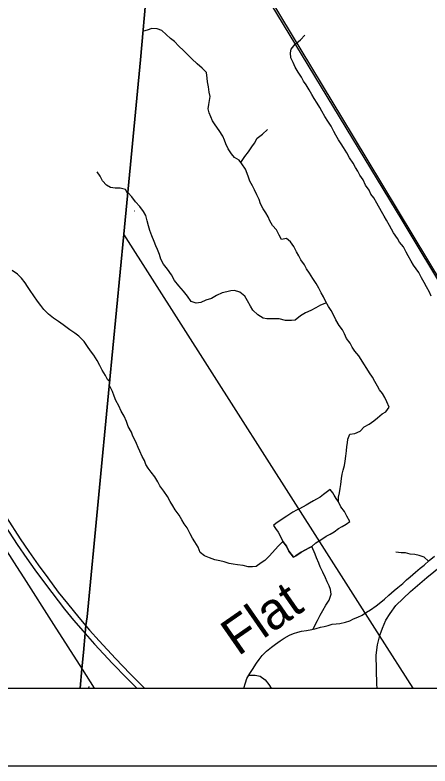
# Model space of a CAD drawing. Extents: x 0 to 34, y 0 to 22.
# Drawn here: x 2.622 to 3.154, y 14 to 14.963 of the extents above; entities that cross this region are included whole.
import ezdxf

# ---------------------------------------------------------------- set-up
doc = ezdxf.new("R2010")
doc.units = 0
for name, color, linetype in [('GM_X_Corporation', 7, 'Continuous'), ('GM_X_Minor_Lake', 7, 'Continuous'), ('GM_X_Minor_River', 7, 'Continuous'), ('GM_X_Minor_River_Text', 7, 'Continuous'), ('GM_X_Rail_Line', 7, 'Continuous'), ('GM_X_State_Route', 7, 'Continuous'), ('GM_X_US_Route', 7, 'Continuous'), ('SH_Data', 7, 'Continuous')]:
    doc.layers.add(name, color=color, linetype=linetype)

msp = doc.modelspace()

# ---------------------------------------------------------------- linework, layer by layer
at = {"layer": 'GM_X_Corporation'}
for points in [[(2.1, 20.9), (2.1, 14.1), (2.70517, 14.1), (2.70761, 14.12453), (2.70949, 14.14572), (2.71149, 14.17029), (2.71244, 14.18008), (2.71408, 14.19146), (2.74262, 14.48729), (2.76121, 14.68204), (2.78252, 14.90567), (2.79096, 14.99744), (2.84444, 15.57923), (2.89388, 16.10066)], [(2.89388, 16.10066), (2.84444, 15.57923), (2.79096, 14.99744), (2.78252, 14.90567), (2.76121, 14.68204), (2.74262, 14.48729), (2.71408, 14.19146), (2.71244, 14.18008), (2.71149, 14.17029), (2.70949, 14.14572), (2.70761, 14.12453), (2.70517, 14.1), (8.9, 14.1)]]:
    msp.add_lwpolyline(points, dxfattribs=at)
for points in [[(2.1, 15.03648), (2.1, 14.1), (2.70517, 14.1), (2.70761, 14.12453), (2.70949, 14.14572), (2.71149, 14.17029), (2.71244, 14.18008), (2.71408, 14.19146), (2.74262, 14.48729), (2.76121, 14.68204), (2.78252, 14.90567), (2.79096, 14.99744), (2.14799, 15.03391), (2.14359, 15.03416), (2.13937, 15.03437), (2.12058, 15.03531), (2.12001, 15.03535)], [(2.70517, 14.1), (3.13256, 14.1), (3.08947, 14.16754), (2.76121, 14.68204), (2.74262, 14.48729), (2.71408, 14.19146), (2.71244, 14.18008), (2.71149, 14.17029), (2.70949, 14.14572), (2.70761, 14.12453)]]:
    msp.add_lwpolyline(points, close=True, dxfattribs=at)
at = {"layer": 'GM_X_Minor_Lake'}
for points in [[(3.0367, 14.33863), (3.0337, 14.34301), (3.03126, 14.34738), (3.02938, 14.35023), (3.02599, 14.35442), (3.01762, 14.34802), (3.01305, 14.34482), (3.00868, 14.34238), (3.0045, 14.33994), (2.99956, 14.33712), (2.99519, 14.33468), (2.98682, 14.3298), (2.98283, 14.32811), (2.97827, 14.32548), (2.97542, 14.32398), (2.97048, 14.32059), (2.96572, 14.31759), (2.96135, 14.31439), (2.95659, 14.31138), (2.95317, 14.30855), (2.95599, 14.30456), (2.95937, 14.29999), (2.96181, 14.29505), (2.96537, 14.28783)], [(3.00234, 14.2816), (3.00761, 14.2861), (3.01408, 14.29005), (3.02092, 14.29494), (3.02586, 14.29737), (3.031, 14.30019), (3.03651, 14.30452), (3.04146, 14.30715), (3.04659, 14.31034), (3.05109, 14.3136), (3.04759, 14.32038), (3.04422, 14.32647), (3.03989, 14.33255), (3.0367, 14.33863)], [(2.96537, 14.28783), (2.96988, 14.28175), (2.97288, 14.27548), (2.97913, 14.26766), (2.98194, 14.26955), (2.9886, 14.27407), (2.9943, 14.27726), (2.99905, 14.2797), (3.00234, 14.2816)]]:
    msp.add_lwpolyline(points, dxfattribs=at)
at = {"layer": 'GM_X_Minor_River'}
msp.add_line((2.71629, 14.1), (2.71669, 14.10206), dxfattribs=at)
for points in [[(2.88823, 14.80795), (2.88353, 14.81498), (2.87827, 14.82241), (2.87526, 14.82735), (2.87282, 14.83267), (2.87095, 14.83761), (2.86947, 14.84273), (2.87025, 14.84842), (2.87123, 14.85353), (2.87201, 14.85865), (2.87071, 14.86434), (2.86999, 14.87098), (2.86851, 14.87743), (2.86834, 14.88236), (2.86724, 14.88938), (2.86178, 14.89491), (2.85536, 14.90044), (2.84858, 14.90692), (2.84235, 14.91283), (2.83764, 14.91778), (2.8318, 14.92312), (2.82614, 14.92903), (2.82124, 14.93322), (2.81558, 14.93837), (2.80992, 14.94314), (2.80406, 14.94563), (2.79743, 14.94585), (2.79135, 14.94361), (2.78633, 14.94233)], [(3.15563, 14.6026), (3.15358, 14.60773), (3.14964, 14.61476), (3.14644, 14.6199), (3.14307, 14.62617), (3.13969, 14.63282), (3.13612, 14.63758), (3.13311, 14.64252), (3.12973, 14.64747), (3.12616, 14.65431), (3.12354, 14.65907), (3.11997, 14.66572), (3.11508, 14.672), (3.11226, 14.67675), (3.10737, 14.68379), (3.10475, 14.68854), (3.10193, 14.6933), (3.09818, 14.69995), (3.09517, 14.70509), (3.09179, 14.71117), (3.08579, 14.72181), (3.08184, 14.72866), (3.07827, 14.73361), (3.07583, 14.73836), (3.07151, 14.74501), (3.06813, 14.75167), (3.064, 14.75775), (3.06156, 14.7627), (3.05855, 14.76764), (3.05536, 14.77296), (3.05066, 14.78019), (3.04728, 14.78647), (3.04296, 14.79312), (3.03995, 14.79788), (3.03657, 14.8032), (3.03338, 14.8091), (3.03075, 14.81385), (3.02738, 14.8205), (3.02286, 14.82697), (3.01929, 14.83287), (3.01535, 14.83971), (3.01272, 14.84465), (3.00953, 14.84998), (3.00558, 14.85607), (3.00239, 14.8612), (2.99901, 14.86709), (2.99525, 14.87356), (2.99187, 14.87851), (2.98905, 14.88364), (2.98491, 14.88973), (2.98116, 14.89638), (2.97835, 14.90246), (2.97572, 14.90835), (2.975, 14.91461), (2.97616, 14.91954), (2.98131, 14.92577), (2.98797, 14.93142), (2.99349, 14.93746)], [(2.91137, 14.77415), (2.91633, 14.78164), (2.9211, 14.78787), (2.92568, 14.79411), (2.92873, 14.79902), (2.93256, 14.80526), (2.9394, 14.81015), (2.94569, 14.81637)], [(3.00234, 14.2816), (3.00761, 14.2861), (3.01408, 14.29005), (3.02092, 14.29494), (3.02586, 14.29737), (3.031, 14.30019), (3.03651, 14.30452), (3.04146, 14.30715), (3.04659, 14.31034), (3.05109, 14.3136), (3.04759, 14.32038), (3.04422, 14.32647), (3.03989, 14.33255), (3.0367, 14.33863), (3.03674, 14.34489), (3.03791, 14.35038), (3.0387, 14.35606), (3.03967, 14.36117), (3.04047, 14.36856), (3.04145, 14.37443), (3.04262, 14.37954), (3.04435, 14.38522), (3.04533, 14.39109), (3.04594, 14.39734), (3.04711, 14.40434), (3.04752, 14.40965), (3.04831, 14.41457), (3.04871, 14.41931), (3.0514, 14.42555), (3.05746, 14.42628), (3.06449, 14.42927), (3.06964, 14.43493), (3.07591, 14.4385), (3.082, 14.44264), (3.08675, 14.4464), (3.09285, 14.45187), (3.0976, 14.45412), (3.10161, 14.46016), (3.09881, 14.46719), (3.09618, 14.4727), (3.09318, 14.47783), (3.08923, 14.48259), (3.08679, 14.48734), (3.08341, 14.49305), (3.08022, 14.49875), (3.07665, 14.50426), (3.07308, 14.50997), (3.06933, 14.51567), (3.06594, 14.52119), (3.06294, 14.52594), (3.05767, 14.53203), (3.05428, 14.53698), (3.05166, 14.54211), (3.04677, 14.5482), (3.04434, 14.55428), (3.0419, 14.55922), (3.03757, 14.56512), (3.03344, 14.57215), (3.02988, 14.57937), (3.02725, 14.58412), (3.02368, 14.58945), (3.02012, 14.5961), (3.01731, 14.60161), (3.0143, 14.60675), (3.01131, 14.61302), (3.00792, 14.61872), (3.00379, 14.62519), (2.99928, 14.63203), (2.99571, 14.63755), (2.9929, 14.64268), (2.98838, 14.64934), (2.98576, 14.65428), (2.98275, 14.65923), (2.97919, 14.66626), (2.97524, 14.67234), (2.96977, 14.67654), (2.96351, 14.67506), (2.96051, 14.68076), (2.95713, 14.6876), (2.95205, 14.69312), (2.94848, 14.69921), (2.94661, 14.70434), (2.94361, 14.70947), (2.94004, 14.7146), (2.93647, 14.72107), (2.93498, 14.72638), (2.93179, 14.73266), (2.92899, 14.73893), (2.92655, 14.74406), (2.92298, 14.75014), (2.92111, 14.75508), (2.91962, 14.76001), (2.91738, 14.76552), (2.91287, 14.77218), (2.9091, 14.77713), (2.90306, 14.78057), (2.89948, 14.78533), (2.89534, 14.79142), (2.89235, 14.79807), (2.89048, 14.80282), (2.88823, 14.80795)], [(2.76658, 14.73378), (2.7635, 14.73923), (2.75669, 14.74124), (2.75004, 14.74096), (2.74416, 14.742), (2.73907, 14.74474), (2.73384, 14.75051), (2.73089, 14.75644), (2.72718, 14.76219)], [(3.02131, 14.59389), (3.01365, 14.59121), (3.00776, 14.58764), (3.00111, 14.58426), (2.99446, 14.58126), (2.988, 14.5775), (2.98114, 14.57185), (2.97622, 14.5715), (2.96864, 14.57154), (2.9605, 14.57367), (2.95538, 14.5735), (2.95008, 14.57334), (2.94477, 14.57337), (2.93985, 14.57434), (2.93305, 14.57855), (2.92683, 14.58483), (2.92364, 14.58959), (2.92008, 14.59662), (2.91651, 14.60251), (2.91009, 14.60766), (2.90328, 14.60978), (2.89855, 14.60962), (2.89342, 14.60832), (2.88735, 14.60683), (2.88013, 14.60327), (2.87367, 14.5997), (2.86665, 14.59727), (2.86019, 14.59446), (2.85412, 14.59373), (2.84769, 14.59585), (2.84318, 14.60251), (2.83791, 14.60898), (2.83188, 14.61603), (2.82623, 14.6225), (2.82248, 14.62991), (2.81741, 14.63733), (2.81233, 14.6438), (2.80876, 14.65007), (2.8069, 14.65596), (2.80428, 14.66223), (2.80222, 14.66735), (2.80017, 14.67286), (2.79736, 14.68008), (2.79456, 14.68673), (2.79288, 14.6928), (2.7914, 14.69906), (2.78954, 14.70609), (2.78673, 14.71103), (2.78184, 14.71769), (2.77637, 14.72378), (2.77167, 14.72987), (2.76672, 14.73526)], [(2.77474, 14.71205), (2.77487, 14.71191)], [(2.74358, 14.4927), (2.74017, 14.49577), (2.73797, 14.50073), (2.73371, 14.50782), (2.73056, 14.51356), (2.72724, 14.51988), (2.72279, 14.52678), (2.7185, 14.53234), (2.7146, 14.5381), (2.71033, 14.54443), (2.7034, 14.55117), (2.69833, 14.55505), (2.69194, 14.55951), (2.68329, 14.56572), (2.67766, 14.57017), (2.67107, 14.57426), (2.6645, 14.57948), (2.6587, 14.58545), (2.65498, 14.59044), (2.65051, 14.59621), (2.64567, 14.60311), (2.64103, 14.61002), (2.63787, 14.61481), (2.63472, 14.61979), (2.62987, 14.62575), (2.62482, 14.63076), (2.61786, 14.63561)], [(3.00434, 14.17562), (3.00665, 14.18111), (3.0099, 14.18678), (3.01316, 14.1934), (3.0166, 14.19925), (3.02043, 14.20606), (3.02482, 14.21286), (3.02733, 14.22023), (3.0266, 14.2263), (3.02455, 14.23105), (3.0223, 14.23618), (3.02006, 14.2415), (3.0165, 14.24872), (3.01331, 14.25537), (3.01163, 14.26011), (3.00864, 14.26695), (3.00677, 14.2717), (3.00234, 14.2816), (2.99905, 14.2797), (2.9943, 14.27726), (2.9886, 14.27407), (2.98194, 14.26955), (2.97913, 14.26766), (2.97288, 14.27548), (2.96988, 14.28175), (2.96537, 14.28783), (2.95908, 14.2818), (2.94802, 14.26935), (2.94212, 14.26351), (2.93736, 14.26069), (2.93108, 14.25598), (2.92634, 14.25544), (2.92085, 14.25547), (2.91423, 14.25721), (2.90722, 14.25819), (2.90135, 14.25898), (2.89624, 14.25976), (2.88981, 14.26169), (2.88451, 14.26304), (2.87808, 14.26459), (2.87127, 14.26709), (2.86465, 14.26959), (2.85918, 14.27379), (2.85657, 14.28062), (2.85244, 14.28747), (2.84943, 14.29222), (2.84643, 14.29754), (2.84249, 14.30533), (2.83854, 14.31047), (2.83573, 14.31579), (2.83217, 14.32187), (2.82728, 14.32834), (2.82408, 14.33347), (2.82071, 14.33937), (2.81752, 14.34583), (2.81282, 14.35248), (2.80736, 14.35915), (2.80474, 14.36446), (2.80099, 14.37093), (2.79628, 14.37702), (2.79233, 14.38196), (2.78933, 14.38672), (2.78765, 14.39184), (2.78502, 14.39697), (2.78165, 14.40362), (2.77978, 14.40837), (2.77754, 14.4135), (2.77548, 14.41825), (2.77285, 14.42319), (2.77098, 14.42794), (2.76686, 14.43554), (2.76462, 14.44199), (2.76162, 14.44864), (2.75787, 14.45492), (2.75468, 14.46176), (2.75093, 14.46879), (2.74869, 14.47448), (2.74683, 14.48018), (2.74364, 14.48645), (2.74307, 14.48742)], [(2.91532, 14.1), (2.91736, 14.10672), (2.91891, 14.11201), (2.92292, 14.11863), (2.92655, 14.12392), (2.93134, 14.13185), (2.93496, 14.13676), (2.93878, 14.14186), (2.94412, 14.14713), (2.95078, 14.15241), (2.95573, 14.15617), (2.96181, 14.16069), (2.96695, 14.16388), (2.97379, 14.16783), (2.97892, 14.16989), (2.98442, 14.17175), (2.98936, 14.17286), (2.99561, 14.17397), (3.00263, 14.17526), (3.00794, 14.17637), (3.01345, 14.17786), (3.01838, 14.17897), (3.0235, 14.18027), (3.02844, 14.18176), (3.03356, 14.18211), (3.03849, 14.18284), (3.0457, 14.18432), (3.0512, 14.18619), (3.05614, 14.18863), (3.06146, 14.19087), (3.06697, 14.1935), (3.07267, 14.19726), (3.07762, 14.20045), (3.08484, 14.20534), (3.09093, 14.21005), (3.09569, 14.214), (3.10122, 14.21928), (3.10826, 14.22493), (3.11302, 14.22908), (3.11911, 14.23416), (3.12406, 14.23887), (3.12882, 14.24264), (3.1353, 14.24867), (3.14158, 14.25356), (3.14653, 14.25752), (3.15281, 14.26355), (3.15967, 14.26901)], [(3.15204, 14.26281), (3.1464, 14.26775), (3.14016, 14.27006), (3.13467, 14.27104), (3.1288, 14.27163), (3.12255, 14.27318), (3.11725, 14.2734), (3.11043, 14.27419)], [(2.92168, 14.11657), (2.92973, 14.11632), (2.93617, 14.11515), (2.94259, 14.11057), (2.94748, 14.10448), (2.95016, 14.1)]]:
    msp.add_lwpolyline(points, dxfattribs=at)
at = {"layer": 'GM_X_Rail_Line'}
for points in [[(3.17806, 14.60062), (3.1182, 14.70018), (2.92606, 15.01768), (2.82675, 15.18408), (2.8108, 15.21209)], [(3.17806, 14.60062), (3.17015, 14.61816), (3.05589, 14.80722), (2.92293, 15.02814), (2.91491, 15.04458), (2.9071, 15.06451), (2.90625, 15.06632)]]:
    msp.add_lwpolyline(points, dxfattribs=at)
at = {"layer": 'GM_X_State_Route'}
msp.add_line((2.70773, 14.12426), (2.72326, 14.1), dxfattribs=at)
for points in [[(2.35052, 14.67799), (2.40066, 14.60059), (2.47292, 14.48933), (2.54926, 14.37109), (2.55934, 14.35546), (2.58143, 14.3212), (2.58566, 14.31471), (2.62352, 14.25595), (2.63286, 14.24132), (2.67118, 14.18133), (2.70773, 14.12426)], [(3.08623, 14.1), (3.08599, 14.10491), (3.08509, 14.14223), (3.08669, 14.15531), (3.08958, 14.16727), (3.08999, 14.1686), (3.09293, 14.17693), (3.09735, 14.18692), (3.10289, 14.19562), (3.1104, 14.20565), (3.12926, 14.22391), (3.1499, 14.24165), (3.16797, 14.25632), (3.18776, 14.27247), (3.20467, 14.2862)]]:
    msp.add_lwpolyline(points, dxfattribs=at)
at = {"layer": 'GM_X_US_Route'}
for points in [[(2.60379, 14.31586), (2.62451, 14.28413), (2.63672, 14.26615), (2.64692, 14.25168), (2.65682, 14.23815), (2.66882, 14.22231), (2.68531, 14.2013), (2.69688, 14.1871), (2.70909, 14.17285), (2.71161, 14.17002)], [(2.61056, 14.31865), (2.6285, 14.29141), (2.63943, 14.27516), (2.65138, 14.25811), (2.66362, 14.24127), (2.67725, 14.22313), (2.68901, 14.20826), (2.7036, 14.19048), (2.71255, 14.17981)], [(2.71255, 14.17981), (2.7173, 14.17427), (2.72945, 14.16058), (2.75042, 14.13771), (2.76932, 14.11815), (2.78768, 14.1)], [(2.71161, 14.17002), (2.72374, 14.15632), (2.74679, 14.13131), (2.76514, 14.11252), (2.7778, 14.1)]]:
    msp.add_lwpolyline(points, dxfattribs=at)
at = {"layer": 'SH_Data'}
for p, q in [((2.1, 14.1), (8.9, 14.1)), ((2, 14), (9, 14))]:
    msp.add_line(p, q, dxfattribs=at)

# ---------------------------------------------------------------- texts
at = {"layer": 'GM_X_Minor_River_Text'}
msp.add_text('Flat', height=0.047349, rotation=34.78619, dxfattribs=at).set_placement((2.90785, 14.14012))

doc.saveas('drawing.dxf')
